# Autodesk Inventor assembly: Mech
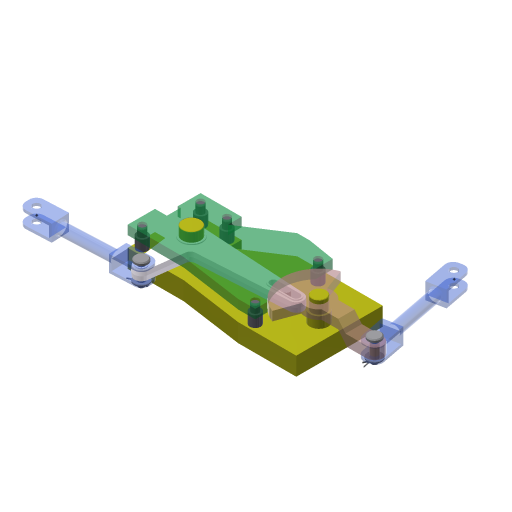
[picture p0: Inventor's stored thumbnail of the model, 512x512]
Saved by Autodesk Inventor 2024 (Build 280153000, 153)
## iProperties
Created: 2023-03
Part Number: Mech
Document SubType Name: Zespół
Designer: Andrzej Jaskulski
Checked By: A.J.
Engr Approved By: Andrzej Jaskulski
Mfg Approved By: Andrzej Jaskulski
Authority: A.J.
Company: ATC
Control State: 0
Master: False
Checked Out: False
Shininess: 64.0
Angle Display Precision: 2
Document Length Units: 11269
Document Angle Units: 11279
Document Time Units: 11290
Document Mass Units: 11283
Document Length Units Precision: 3
Document Angle Units Precision: 2
Density: 0.0
Volumn: 0.0
Area: 0.0
PropertySet Name: Model Information
Title: A.J.: Kurs R2024-MEP
Author: Andrzej Jaskulski
Revision Number: 1/24
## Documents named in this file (8)
- C:\Users\AndJas\Documents\R2024-MEP\Obszar roboczy\Mech-Gotowy.iam
- C:\Users\AndJas\Documents\R2024-MEP\Obszar roboczy\C1.ipt
- C:\Users\AndJas\Documents\R2024-MEP\Obszar roboczy\C2.ipt
- C:\Users\AndJas\Documents\R2024-MEP\Obszar roboczy\C3.ipt
- C:\Users\AndJas\Documents\R2024-MEP\Obszar roboczy\C.ipt
- C:\Users\AndJas\Documents\R2024-MEP\Obszar roboczy\C4.ipt
- C:\Users\AndJas\Documents\R2024-MEP\Obszar roboczy\C5.ipt
- C:\Users\AndJas\Documents\R2024-MEP\Obszar roboczy\L1.iam
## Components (13 placed, 7 different names)
1. C:1 — Zestawiające:1, Zestawiające:2, Zestawiające:3, Napędowe, Zestawiające:4, Zestawiające:5, Suwak1, Suwak2
2. C1:1 — Wstawiające:6, Zestawiające:4
3. C2:1 — Zestawiające:3, Przejściowy:1, Zestawiające:5, Walce, Płaszczyzny
4. C3:1
5. C3:2 — Wstawiające:6
6. C3:3
7. C3:4
8. C3:5
9. C5:1 — Suwak1, Walce, Płaszczyzny, Wstaw:7
10. L1:1 [sub-assembly] — Wstaw:7
11. C5:2 — Suwak2, Walec, Wstaw:8
12. L1:2 [sub-assembly] — Wstaw:8
13. C4:1 — Zestawiające:1, Zestawiające:2, Przejściowy:1, Napędowe, Walec
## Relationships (15: Mate 10, Insert 3, Transitional 1, Angle 1)
- Zestawiające:1 [Mate]: C:1 ↔ C4:1
- Zestawiające:2 [Mate]: C:1 ↔ C4:1
- Zestawiające:3 [Mate]: C:1 ↔ C2:1
- Przejściowy:1 [Transitional]: C2:1 ↔ C4:1
- Napędowe [Angle]: C:1 ↔ C4:1
- Wstawiające:6 [Insert]: C1:1 ↔ C3:2
- Zestawiające:4 [Mate]: C:1 ↔ C1:1
- Zestawiające:5 [Mate]: C:1 ↔ C2:1
- Suwak1 [Mate]: C:1 ↔ C5:1
- Suwak2 [Mate]: C:1 ↔ C5:2
- Walce [Mate]: C2:1 ↔ C5:1
- Płaszczyzny [Mate]: C2:1 ↔ C5:1
- Walec [Mate]: C5:2 ↔ C4:1
- Wstaw:7 [Insert]: C5:1 ↔ L1:1
- Wstaw:8 [Insert]: C5:2 ↔ L1:2
